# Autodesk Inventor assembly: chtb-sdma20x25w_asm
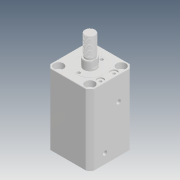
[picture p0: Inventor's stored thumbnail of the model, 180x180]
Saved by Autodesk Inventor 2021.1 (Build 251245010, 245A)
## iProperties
Company: Microsoft
Created: 2018-05
Part Number: chtb-sdma20x25w_asm
Description: STEP AP214
Document SubType Name: Assembly
Designer: user
Title: chtb-sdma20x25w_asm.STEP
Author: Windows
Revision Number: ÈÎºÎ
Sending System: SolidWorks 2015
Preprocessor: SwSTEP 2.0
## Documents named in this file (4)
- D:\Vault_2016\Projekty\Clamptek\Hydraulic\CHTB\CHTB-20\Inventor\CHTB-SDMA20x25W\chtb-sdma20x25w_asm.iam
- D:\Vault_2016\Projekty\Clamptek\Hydraulic\CHTB\CHTB-20\Inventor\CHTB-SDMA20x25W\CHTB-SDMA20X25NBT.ipt
- D:\Vault_2016\Projekty\Clamptek\Hydraulic\CHTB\CHTB-20\Inventor\CHTB-SDMA20x25W\QG_3.ipt
- D:\Vault_2016\Projekty\Clamptek\Hydraulic\CHTB\CHTB-20\Inventor\CHTB-SDMA20x25W\CHTB-SDMA20X25WHSG.ipt
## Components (3 placed, 3 different names)
1. CHTB-SDMA20X25NBT_1
2. QG_3_2
3. CHTB-SDMA20X25WHSG_3
